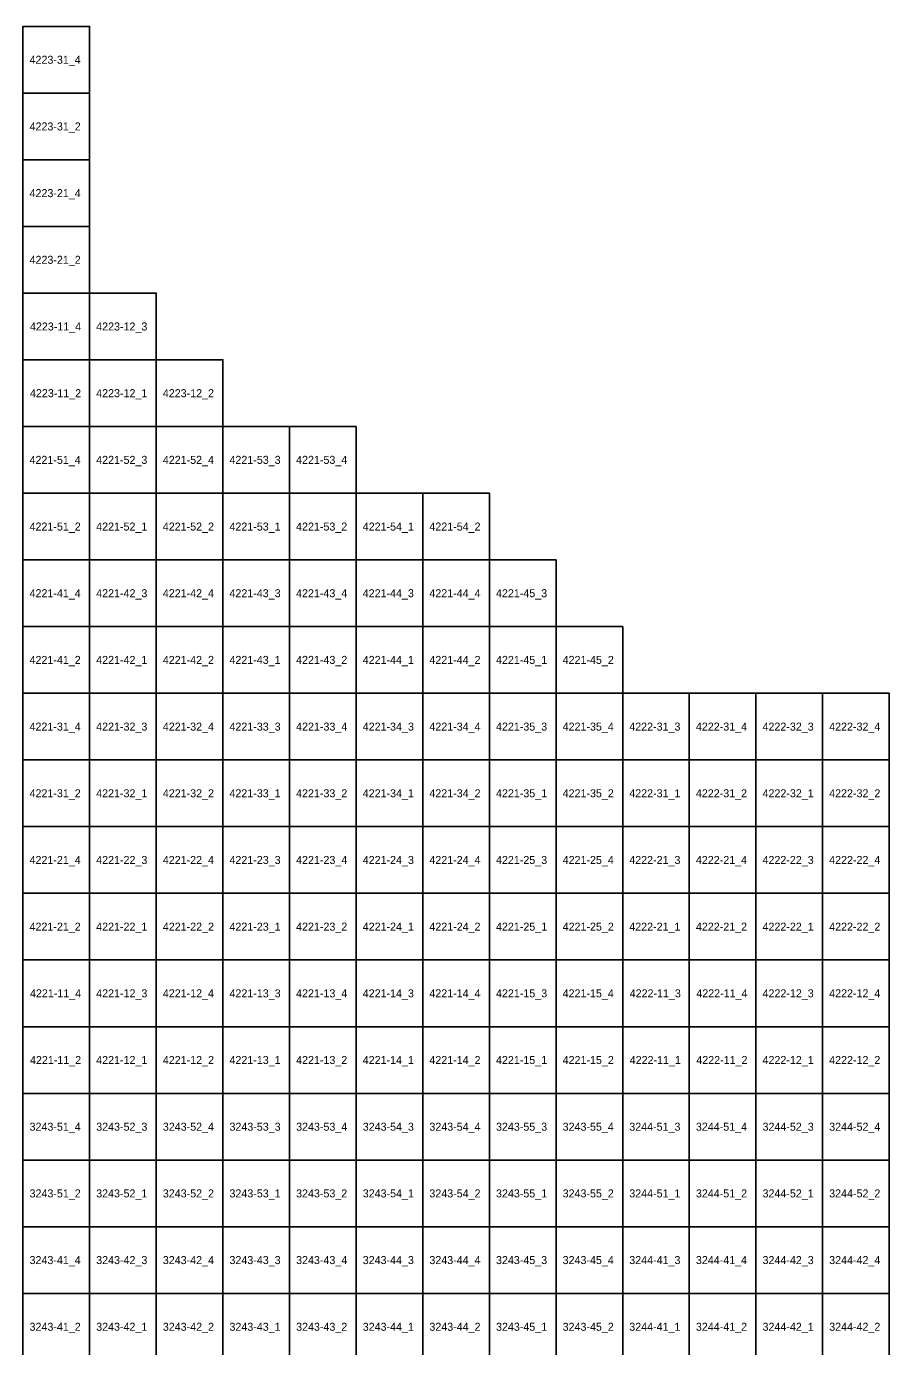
# Model space of a CAD drawing. Extents: x 312500 to 765000, y 172500 to 440000.
# Drawn here: x 452629 to 484827, y 290507 to 340000 of the extents above; entities that cross this region are included whole.
import ezdxf

# ---------------------------------------------------------------- set-up
doc = ezdxf.new("R2010")
doc.units = 0
doc.layers.add('Topo5_ramis_TKS2025', color=7, linetype='Continuous')
doc.layers.add('Topo5_ramis_TKS2025_Nr', color=7, linetype='Continuous')

msp = doc.modelspace()

# ---------------------------------------------------------------- linework, layer by layer
at = {"layer": 'Topo5_ramis_TKS2025'}
for points in [[(452500, 337500), (452500, 340000), (455000, 340000), (455000, 337500), (452500, 337500)], [(452500, 335000), (452500, 337500), (455000, 337500), (455000, 335000), (452500, 335000)], [(452500, 332500), (452500, 335000), (455000, 335000), (455000, 332500), (452500, 332500)], [(452500, 330000), (452500, 332500), (455000, 332500), (455000, 330000), (452500, 330000)], [(452500, 327500), (452500, 330000), (455000, 330000), (455000, 327500), (452500, 327500)], [(455000, 327500), (455000, 330000), (457500, 330000), (457500, 327500), (455000, 327500)], [(452500, 325000), (452500, 327500), (455000, 327500), (455000, 325000), (452500, 325000)], [(455000, 325000), (455000, 327500), (457500, 327500), (457500, 325000), (455000, 325000)], [(457500, 325000), (457500, 327500), (460000, 327500), (460000, 325000), (457500, 325000)], [(452500, 322500), (452500, 325000), (455000, 325000), (455000, 322500), (452500, 322500)], [(455000, 322500), (455000, 325000), (457500, 325000), (457500, 322500), (455000, 322500)], [(457500, 322500), (457500, 325000), (460000, 325000), (460000, 322500), (457500, 322500)], [(460000, 322500), (460000, 325000), (462500, 325000), (462500, 322500), (460000, 322500)], [(462500, 322500), (462500, 325000), (465000, 325000), (465000, 322500), (462500, 322500)], [(452500, 320000), (452500, 322500), (455000, 322500), (455000, 320000), (452500, 320000)], [(455000, 320000), (455000, 322500), (457500, 322500), (457500, 320000), (455000, 320000)], [(457500, 320000), (457500, 322500), (460000, 322500), (460000, 320000), (457500, 320000)], [(460000, 320000), (460000, 322500), (462500, 322500), (462500, 320000), (460000, 320000)], [(462500, 320000), (462500, 322500), (465000, 322500), (465000, 320000), (462500, 320000)], [(465000, 320000), (465000, 322500), (467500, 322500), (467500, 320000), (465000, 320000)], [(467500, 320000), (467500, 322500), (470000, 322500), (470000, 320000), (467500, 320000)], [(452500, 317500), (452500, 320000), (455000, 320000), (455000, 317500), (452500, 317500)], [(455000, 317500), (455000, 320000), (457500, 320000), (457500, 317500), (455000, 317500)], [(457500, 317500), (457500, 320000), (460000, 320000), (460000, 317500), (457500, 317500)], [(460000, 317500), (460000, 320000), (462500, 320000), (462500, 317500), (460000, 317500)], [(462500, 317500), (462500, 320000), (465000, 320000), (465000, 317500), (462500, 317500)], [(465000, 317500), (465000, 320000), (467500, 320000), (467500, 317500), (465000, 317500)], [(467500, 317500), (467500, 320000), (470000, 320000), (470000, 317500), (467500, 317500)], [(470000, 317500), (470000, 320000), (472500, 320000), (472500, 317500), (470000, 317500)], [(452500, 315000), (452500, 317500), (455000, 317500), (455000, 315000), (452500, 315000)], [(455000, 315000), (455000, 317500), (457500, 317500), (457500, 315000), (455000, 315000)], [(457500, 315000), (457500, 317500), (460000, 317500), (460000, 315000), (457500, 315000)], [(460000, 315000), (460000, 317500), (462500, 317500), (462500, 315000), (460000, 315000)], [(462500, 315000), (462500, 317500), (465000, 317500), (465000, 315000), (462500, 315000)], [(465000, 315000), (465000, 317500), (467500, 317500), (467500, 315000), (465000, 315000)], [(467500, 315000), (467500, 317500), (470000, 317500), (470000, 315000), (467500, 315000)], [(470000, 315000), (470000, 317500), (472500, 317500), (472500, 315000), (470000, 315000)], [(472500, 315000), (472500, 317500), (475000, 317500), (475000, 315000), (472500, 315000)], [(452500, 312500), (452500, 315000), (455000, 315000), (455000, 312500), (452500, 312500)], [(455000, 312500), (455000, 315000), (457500, 315000), (457500, 312500), (455000, 312500)], [(457500, 312500), (457500, 315000), (460000, 315000), (460000, 312500), (457500, 312500)], [(460000, 312500), (460000, 315000), (462500, 315000), (462500, 312500), (460000, 312500)], [(462500, 312500), (462500, 315000), (465000, 315000), (465000, 312500), (462500, 312500)], [(465000, 312500), (465000, 315000), (467500, 315000), (467500, 312500), (465000, 312500)], [(467500, 312500), (467500, 315000), (470000, 315000), (470000, 312500), (467500, 312500)], [(470000, 312500), (470000, 315000), (472500, 315000), (472500, 312500), (470000, 312500)], [(472500, 312500), (472500, 315000), (475000, 315000), (475000, 312500), (472500, 312500)], [(475000, 312500), (475000, 315000), (477500, 315000), (477500, 312500), (475000, 312500)], [(477500, 312500), (477500, 315000), (480000, 315000), (480000, 312500), (477500, 312500)], [(480000, 312500), (480000, 315000), (482500, 315000), (482500, 312500), (480000, 312500)], [(482500, 312500), (482500, 315000), (485000, 315000), (485000, 312500), (482500, 312500)], [(452500, 310000), (452500, 312500), (455000, 312500), (455000, 310000), (452500, 310000)], [(455000, 310000), (455000, 312500), (457500, 312500), (457500, 310000), (455000, 310000)], [(457500, 310000), (457500, 312500), (460000, 312500), (460000, 310000), (457500, 310000)], [(460000, 310000), (460000, 312500), (462500, 312500), (462500, 310000), (460000, 310000)], [(462500, 310000), (462500, 312500), (465000, 312500), (465000, 310000), (462500, 310000)], [(465000, 310000), (465000, 312500), (467500, 312500), (467500, 310000), (465000, 310000)], [(467500, 310000), (467500, 312500), (470000, 312500), (470000, 310000), (467500, 310000)], [(470000, 310000), (470000, 312500), (472500, 312500), (472500, 310000), (470000, 310000)], [(472500, 310000), (472500, 312500), (475000, 312500), (475000, 310000), (472500, 310000)], [(475000, 310000), (475000, 312500), (477500, 312500), (477500, 310000), (475000, 310000)], [(477500, 310000), (477500, 312500), (480000, 312500), (480000, 310000), (477500, 310000)], [(480000, 310000), (480000, 312500), (482500, 312500), (482500, 310000), (480000, 310000)], [(482500, 310000), (482500, 312500), (485000, 312500), (485000, 310000), (482500, 310000)], [(452500, 307500), (452500, 310000), (455000, 310000), (455000, 307500), (452500, 307500)], [(455000, 307500), (455000, 310000), (457500, 310000), (457500, 307500), (455000, 307500)], [(457500, 307500), (457500, 310000), (460000, 310000), (460000, 307500), (457500, 307500)], [(460000, 307500), (460000, 310000), (462500, 310000), (462500, 307500), (460000, 307500)], [(462500, 307500), (462500, 310000), (465000, 310000), (465000, 307500), (462500, 307500)], [(465000, 307500), (465000, 310000), (467500, 310000), (467500, 307500), (465000, 307500)], [(467500, 307500), (467500, 310000), (470000, 310000), (470000, 307500), (467500, 307500)], [(470000, 307500), (470000, 310000), (472500, 310000), (472500, 307500), (470000, 307500)], [(472500, 307500), (472500, 310000), (475000, 310000), (475000, 307500), (472500, 307500)], [(475000, 307500), (475000, 310000), (477500, 310000), (477500, 307500), (475000, 307500)], [(477500, 307500), (477500, 310000), (480000, 310000), (480000, 307500), (477500, 307500)], [(480000, 307500), (480000, 310000), (482500, 310000), (482500, 307500), (480000, 307500)], [(482500, 307500), (482500, 310000), (485000, 310000), (485000, 307500), (482500, 307500)], [(452500, 305000), (452500, 307500), (455000, 307500), (455000, 305000), (452500, 305000)], [(455000, 305000), (455000, 307500), (457500, 307500), (457500, 305000), (455000, 305000)], [(457500, 305000), (457500, 307500), (460000, 307500), (460000, 305000), (457500, 305000)], [(460000, 305000), (460000, 307500), (462500, 307500), (462500, 305000), (460000, 305000)], [(462500, 305000), (462500, 307500), (465000, 307500), (465000, 305000), (462500, 305000)], [(465000, 305000), (465000, 307500), (467500, 307500), (467500, 305000), (465000, 305000)], [(467500, 305000), (467500, 307500), (470000, 307500), (470000, 305000), (467500, 305000)], [(470000, 305000), (470000, 307500), (472500, 307500), (472500, 305000), (470000, 305000)], [(472500, 305000), (472500, 307500), (475000, 307500), (475000, 305000), (472500, 305000)], [(475000, 305000), (475000, 307500), (477500, 307500), (477500, 305000), (475000, 305000)], [(477500, 305000), (477500, 307500), (480000, 307500), (480000, 305000), (477500, 305000)], [(480000, 305000), (480000, 307500), (482500, 307500), (482500, 305000), (480000, 305000)], [(482500, 305000), (482500, 307500), (485000, 307500), (485000, 305000), (482500, 305000)], [(452500, 302500), (452500, 305000), (455000, 305000), (455000, 302500), (452500, 302500)], [(455000, 302500), (455000, 305000), (457500, 305000), (457500, 302500), (455000, 302500)], [(457500, 302500), (457500, 305000), (460000, 305000), (460000, 302500), (457500, 302500)], [(460000, 302500), (460000, 305000), (462500, 305000), (462500, 302500), (460000, 302500)], [(462500, 302500), (462500, 305000), (465000, 305000), (465000, 302500), (462500, 302500)], [(465000, 302500), (465000, 305000), (467500, 305000), (467500, 302500), (465000, 302500)], [(467500, 302500), (467500, 305000), (470000, 305000), (470000, 302500), (467500, 302500)], [(470000, 302500), (470000, 305000), (472500, 305000), (472500, 302500), (470000, 302500)], [(472500, 302500), (472500, 305000), (475000, 305000), (475000, 302500), (472500, 302500)], [(475000, 302500), (475000, 305000), (477500, 305000), (477500, 302500), (475000, 302500)], [(477500, 302500), (477500, 305000), (480000, 305000), (480000, 302500), (477500, 302500)], [(480000, 302500), (480000, 305000), (482500, 305000), (482500, 302500), (480000, 302500)], [(482500, 302500), (482500, 305000), (485000, 305000), (485000, 302500), (482500, 302500)], [(452500, 300000), (452500, 302500), (455000, 302500), (455000, 300000), (452500, 300000)], [(455000, 300000), (455000, 302500), (457500, 302500), (457500, 300000), (455000, 300000)], [(457500, 300000), (457500, 302500), (460000, 302500), (460000, 300000), (457500, 300000)], [(460000, 300000), (460000, 302500), (462500, 302500), (462500, 300000), (460000, 300000)], [(462500, 300000), (462500, 302500), (465000, 302500), (465000, 300000), (462500, 300000)], [(465000, 300000), (465000, 302500), (467500, 302500), (467500, 300000), (465000, 300000)], [(467500, 300000), (467500, 302500), (470000, 302500), (470000, 300000), (467500, 300000)], [(470000, 300000), (470000, 302500), (472500, 302500), (472500, 300000), (470000, 300000)], [(472500, 300000), (472500, 302500), (475000, 302500), (475000, 300000), (472500, 300000)], [(475000, 300000), (475000, 302500), (477500, 302500), (477500, 300000), (475000, 300000)], [(477500, 300000), (477500, 302500), (480000, 302500), (480000, 300000), (477500, 300000)], [(480000, 300000), (480000, 302500), (482500, 302500), (482500, 300000), (480000, 300000)], [(482500, 300000), (482500, 302500), (485000, 302500), (485000, 300000), (482500, 300000)], [(452500, 297500), (452500, 300000), (455000, 300000), (455000, 297500), (452500, 297500)], [(455000, 297500), (455000, 300000), (457500, 300000), (457500, 297500), (455000, 297500)], [(457500, 297500), (457500, 300000), (460000, 300000), (460000, 297500), (457500, 297500)], [(460000, 297500), (460000, 300000), (462500, 300000), (462500, 297500), (460000, 297500)], [(462500, 297500), (462500, 300000), (465000, 300000), (465000, 297500), (462500, 297500)], [(465000, 297500), (465000, 300000), (467500, 300000), (467500, 297500), (465000, 297500)], [(467500, 297500), (467500, 300000), (470000, 300000), (470000, 297500), (467500, 297500)], [(470000, 297500), (470000, 300000), (472500, 300000), (472500, 297500), (470000, 297500)], [(472500, 297500), (472500, 300000), (475000, 300000), (475000, 297500), (472500, 297500)], [(475000, 297500), (475000, 300000), (477500, 300000), (477500, 297500), (475000, 297500)], [(477500, 297500), (477500, 300000), (480000, 300000), (480000, 297500), (477500, 297500)], [(480000, 297500), (480000, 300000), (482500, 300000), (482500, 297500), (480000, 297500)], [(482500, 297500), (482500, 300000), (485000, 300000), (485000, 297500), (482500, 297500)], [(452500, 295000), (452500, 297500), (455000, 297500), (455000, 295000), (452500, 295000)], [(455000, 295000), (455000, 297500), (457500, 297500), (457500, 295000), (455000, 295000)], [(457500, 295000), (457500, 297500), (460000, 297500), (460000, 295000), (457500, 295000)], [(460000, 295000), (460000, 297500), (462500, 297500), (462500, 295000), (460000, 295000)], [(462500, 295000), (462500, 297500), (465000, 297500), (465000, 295000), (462500, 295000)], [(465000, 295000), (465000, 297500), (467500, 297500), (467500, 295000), (465000, 295000)], [(467500, 295000), (467500, 297500), (470000, 297500), (470000, 295000), (467500, 295000)], [(470000, 295000), (470000, 297500), (472500, 297500), (472500, 295000), (470000, 295000)], [(472500, 295000), (472500, 297500), (475000, 297500), (475000, 295000), (472500, 295000)], [(475000, 295000), (475000, 297500), (477500, 297500), (477500, 295000), (475000, 295000)], [(477500, 295000), (477500, 297500), (480000, 297500), (480000, 295000), (477500, 295000)], [(480000, 295000), (480000, 297500), (482500, 297500), (482500, 295000), (480000, 295000)], [(482500, 295000), (482500, 297500), (485000, 297500), (485000, 295000), (482500, 295000)], [(452500, 292500), (452500, 295000), (455000, 295000), (455000, 292500), (452500, 292500)], [(455000, 292500), (455000, 295000), (457500, 295000), (457500, 292500), (455000, 292500)], [(457500, 292500), (457500, 295000), (460000, 295000), (460000, 292500), (457500, 292500)], [(460000, 292500), (460000, 295000), (462500, 295000), (462500, 292500), (460000, 292500)], [(462500, 292500), (462500, 295000), (465000, 295000), (465000, 292500), (462500, 292500)], [(465000, 292500), (465000, 295000), (467500, 295000), (467500, 292500), (465000, 292500)], [(467500, 292500), (467500, 295000), (470000, 295000), (470000, 292500), (467500, 292500)], [(470000, 292500), (470000, 295000), (472500, 295000), (472500, 292500), (470000, 292500)], [(472500, 292500), (472500, 295000), (475000, 295000), (475000, 292500), (472500, 292500)], [(475000, 292500), (475000, 295000), (477500, 295000), (477500, 292500), (475000, 292500)], [(477500, 292500), (477500, 295000), (480000, 295000), (480000, 292500), (477500, 292500)], [(480000, 292500), (480000, 295000), (482500, 295000), (482500, 292500), (480000, 292500)], [(482500, 292500), (482500, 295000), (485000, 295000), (485000, 292500), (482500, 292500)], [(452500, 290000), (452500, 292500), (455000, 292500), (455000, 290000), (452500, 290000)], [(455000, 290000), (455000, 292500), (457500, 292500), (457500, 290000), (455000, 290000)], [(457500, 290000), (457500, 292500), (460000, 292500), (460000, 290000), (457500, 290000)], [(460000, 290000), (460000, 292500), (462500, 292500), (462500, 290000), (460000, 290000)], [(462500, 290000), (462500, 292500), (465000, 292500), (465000, 290000), (462500, 290000)], [(465000, 290000), (465000, 292500), (467500, 292500), (467500, 290000), (465000, 290000)], [(467500, 290000), (467500, 292500), (470000, 292500), (470000, 290000), (467500, 290000)], [(470000, 290000), (470000, 292500), (472500, 292500), (472500, 290000), (470000, 290000)], [(472500, 290000), (472500, 292500), (475000, 292500), (475000, 290000), (472500, 290000)], [(475000, 290000), (475000, 292500), (477500, 292500), (477500, 290000), (475000, 290000)], [(477500, 290000), (477500, 292500), (480000, 292500), (480000, 290000), (477500, 290000)], [(480000, 290000), (480000, 292500), (482500, 292500), (482500, 290000), (480000, 290000)], [(482500, 290000), (482500, 292500), (485000, 292500), (485000, 290000), (482500, 290000)]]:
    msp.add_lwpolyline(points, dxfattribs=at)

# ---------------------------------------------------------------- texts
at = {"layer": 'Topo5_ramis_TKS2025_Nr'}
for s, p in [('4223-31_4', (452748, 338600)), ('4223-31_2', (452748, 336100)), ('4223-21_4', (452748, 333600)), ('4223-21_2', (452748, 331100)), ('4223-11_4', (452764, 328600)), ('4223-12_3', (455248, 328600)), ('4223-11_2', (452764, 326100)), ('4223-12_1', (455248, 326100)), ('4223-12_2', (457748, 326100)), ('4221-51_4', (452748, 323600)), ('4221-52_3', (455248, 323600)), ('4221-52_4', (457748, 323600)), ('4221-53_3', (460248, 323600)), ('4221-53_4', (462748, 323600)), ('4221-51_2', (452748, 321100)), ('4221-52_1', (455248, 321100)), ('4221-52_2', (457748, 321100)), ('4221-53_1', (460248, 321100)), ('4221-53_2', (462748, 321100)), ('4221-54_1', (465248, 321100)), ('4221-54_2', (467748, 321100)), ('4221-41_4', (452748, 318600)), ('4221-42_3', (455248, 318600)), ('4221-42_4', (457748, 318600)), ('4221-43_3', (460248, 318600)), ('4221-43_4', (462748, 318600)), ('4221-44_3', (465248, 318600)), ('4221-44_4', (467748, 318600)), ('4221-45_3', (470248, 318600)), ('4221-41_2', (452748, 316100)), ('4221-42_1', (455248, 316100)), ('4221-42_2', (457748, 316100)), ('4221-43_1', (460248, 316100)), ('4221-43_2', (462748, 316100)), ('4221-44_1', (465248, 316100)), ('4221-44_2', (467748, 316100)), ('4221-45_1', (470248, 316100)), ('4221-45_2', (472748, 316100)), ('4221-31_4', (452748, 313600)), ('4221-32_3', (455248, 313600)), ('4221-32_4', (457748, 313600)), ('4221-33_3', (460248, 313600)), ('4221-33_4', (462748, 313600)), ('4221-34_3', (465248, 313600)), ('4221-34_4', (467748, 313600)), ('4221-35_3', (470248, 313600)), ('4221-35_4', (472748, 313600)), ('4222-31_3', (475248, 313600)), ('4222-31_4', (477748, 313600)), ('4222-32_3', (480248, 313600)), ('4222-32_4', (482748, 313600)), ('4221-31_2', (452748, 311100)), ('4221-32_1', (455248, 311100)), ('4221-32_2', (457748, 311100)), ('4221-33_1', (460248, 311100)), ('4221-33_2', (462748, 311100)), ('4221-34_1', (465248, 311100)), ('4221-34_2', (467748, 311100)), ('4221-35_1', (470248, 311100)), ('4221-35_2', (472748, 311100)), ('4222-31_1', (475248, 311100)), ('4222-31_2', (477748, 311100)), ('4222-32_1', (480248, 311100)), ('4222-32_2', (482748, 311100)), ('4221-21_4', (452748, 308600)), ('4221-22_3', (455248, 308600)), ('4221-22_4', (457748, 308600)), ('4221-23_3', (460248, 308600)), ('4221-23_4', (462748, 308600)), ('4221-24_3', (465248, 308600)), ('4221-24_4', (467748, 308600)), ('4221-25_3', (470248, 308600)), ('4221-25_4', (472748, 308600)), ('4222-21_3', (475248, 308600)), ('4222-21_4', (477748, 308600)), ('4222-22_3', (480248, 308600)), ('4222-22_4', (482748, 308600)), ('4221-21_2', (452748, 306100)), ('4221-22_1', (455248, 306100)), ('4221-22_2', (457748, 306100)), ('4221-23_1', (460248, 306100)), ('4221-23_2', (462748, 306100)), ('4221-24_1', (465248, 306100)), ('4221-24_2', (467748, 306100)), ('4221-25_1', (470248, 306100)), ('4221-25_2', (472748, 306100)), ('4222-21_1', (475248, 306100)), ('4222-21_2', (477748, 306100)), ('4222-22_1', (480248, 306100)), ('4222-22_2', (482748, 306100)), ('4221-11_4', (452764, 303600)), ('4221-12_3', (455248, 303600)), ('4221-12_4', (457748, 303600)), ('4221-13_3', (460248, 303600)), ('4221-13_4', (462748, 303600)), ('4221-14_3', (465248, 303600)), ('4221-14_4', (467748, 303600)), ('4221-15_3', (470248, 303600)), ('4221-15_4', (472748, 303600)), ('4222-11_3', (475264, 303600)), ('4222-11_4', (477764, 303600)), ('4222-12_3', (480248, 303600)), ('4222-12_4', (482748, 303600)), ('4221-11_2', (452764, 301100)), ('4221-12_1', (455248, 301100)), ('4221-12_2', (457748, 301100)), ('4221-13_1', (460248, 301100)), ('4221-13_2', (462748, 301100)), ('4221-14_1', (465248, 301100)), ('4221-14_2', (467748, 301100)), ('4221-15_1', (470248, 301100)), ('4221-15_2', (472748, 301100)), ('4222-11_1', (475264, 301100)), ('4222-11_2', (477764, 301100)), ('4222-12_1', (480248, 301100)), ('4222-12_2', (482748, 301100)), ('3243-51_4', (452748, 298600)), ('3243-52_3', (455248, 298600)), ('3243-52_4', (457748, 298600)), ('3243-53_3', (460248, 298600)), ('3243-53_4', (462748, 298600)), ('3243-54_3', (465248, 298600)), ('3243-54_4', (467748, 298600)), ('3243-55_3', (470248, 298600)), ('3243-55_4', (472748, 298600)), ('3244-51_3', (475248, 298600)), ('3244-51_4', (477748, 298600)), ('3244-52_3', (480248, 298600)), ('3244-52_4', (482748, 298600)), ('3243-51_2', (452748, 296100)), ('3243-52_1', (455248, 296100)), ('3243-52_2', (457748, 296100)), ('3243-53_1', (460248, 296100)), ('3243-53_2', (462748, 296100)), ('3243-54_1', (465248, 296100)), ('3243-54_2', (467748, 296100)), ('3243-55_1', (470248, 296100)), ('3243-55_2', (472748, 296100)), ('3244-51_1', (475248, 296100)), ('3244-51_2', (477748, 296100)), ('3244-52_1', (480248, 296100)), ('3244-52_2', (482748, 296100)), ('3243-41_4', (452748, 293600)), ('3243-42_3', (455248, 293600)), ('3243-42_4', (457748, 293600)), ('3243-43_3', (460248, 293600)), ('3243-43_4', (462748, 293600)), ('3243-44_3', (465248, 293600)), ('3243-44_4', (467748, 293600)), ('3243-45_3', (470248, 293600)), ('3243-45_4', (472748, 293600)), ('3244-41_3', (475248, 293600)), ('3244-41_4', (477748, 293600)), ('3244-42_3', (480248, 293600)), ('3244-42_4', (482748, 293600)), ('3243-41_2', (452748, 291100)), ('3243-42_1', (455248, 291100)), ('3243-42_2', (457748, 291100)), ('3243-43_1', (460248, 291100)), ('3243-43_2', (462748, 291100)), ('3243-44_1', (465248, 291100)), ('3243-44_2', (467748, 291100)), ('3243-45_1', (470248, 291100)), ('3243-45_2', (472748, 291100)), ('3244-41_1', (475248, 291100)), ('3244-41_2', (477748, 291100)), ('3244-42_1', (480248, 291100)), ('3244-42_2', (482748, 291100))]:
    msp.add_text(s, height=300, dxfattribs=at).set_placement(p)

doc.saveas('drawing.dxf')
